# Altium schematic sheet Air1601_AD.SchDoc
size 431 x 279 mm
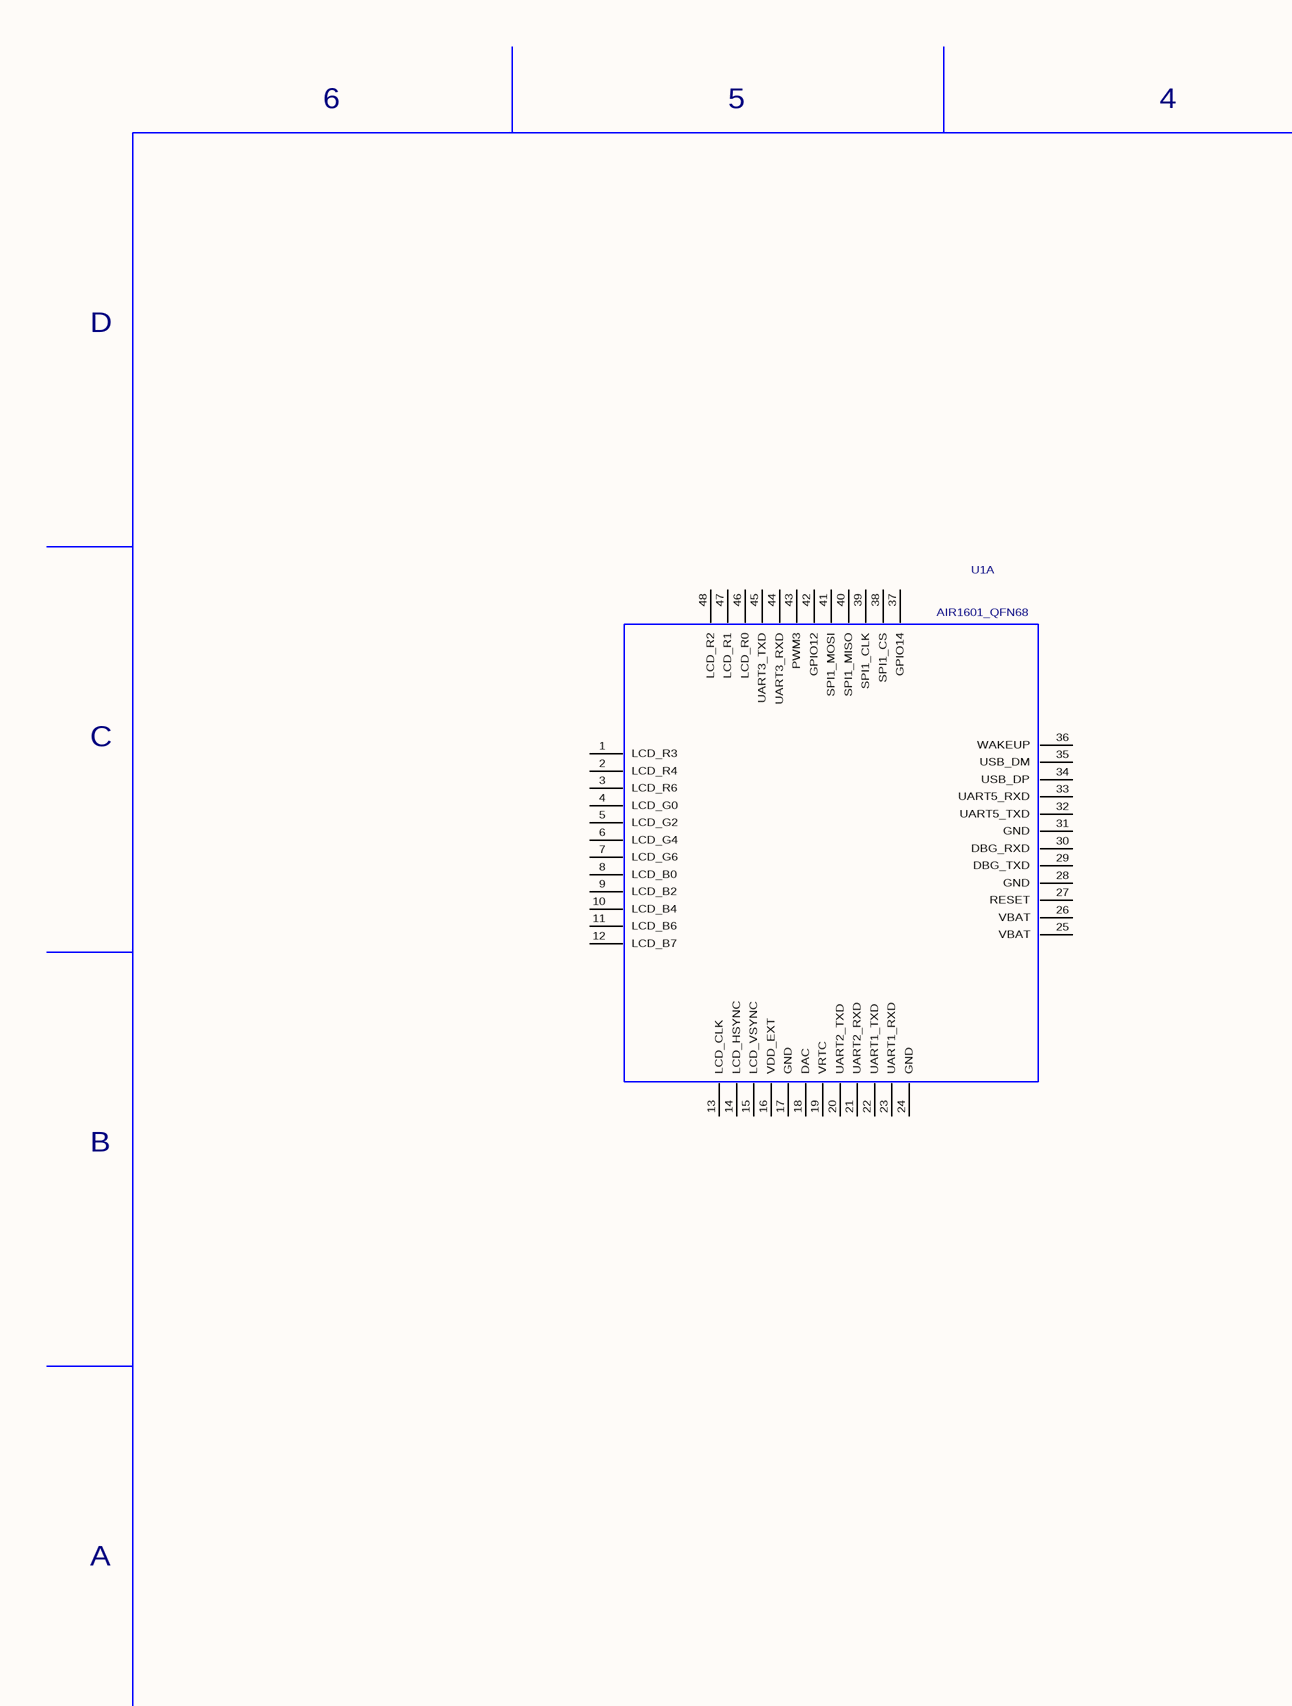
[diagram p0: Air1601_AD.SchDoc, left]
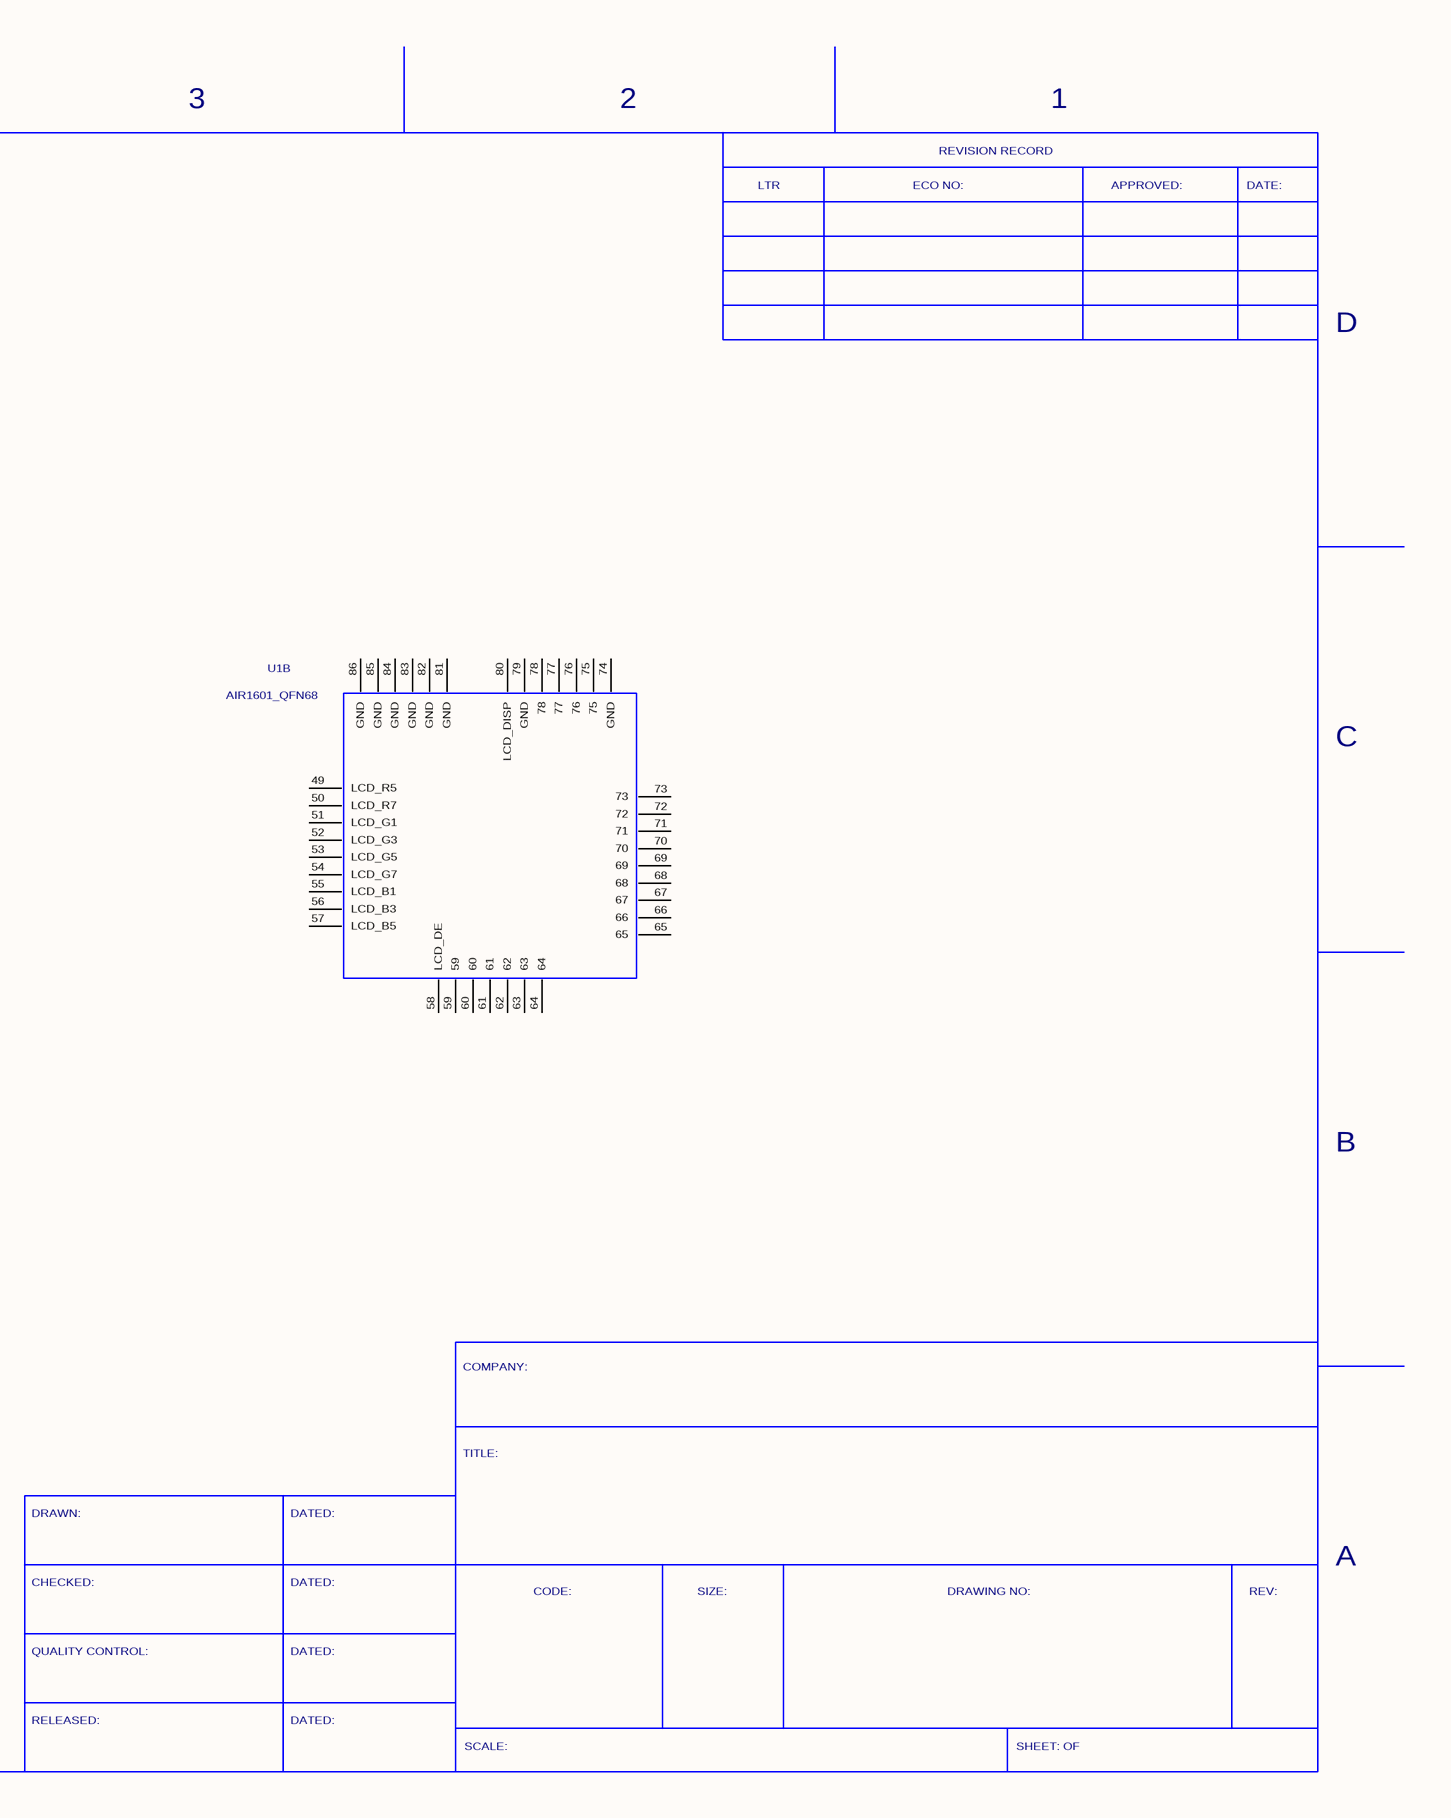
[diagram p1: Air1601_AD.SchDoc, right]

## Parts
U1  AIR1601_QFN68  [AIR1601_19X20]  (parts A,B of 2)

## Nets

Not connected (* = marked no-connect by the designer): U1 1(LCD_R3) 2(LCD_R4) 3(LCD_R6) 4(LCD_G0) 5(LCD_G2) 6(LCD_G4) 7(LCD_G6) 8(LCD_B0) 9(LCD_B2) 10(LCD_B4) 11(LCD_B6) 12(LCD_B7) 13(LCD_CLK) 14(LCD_HSYNC) 15(LCD_VSYNC) 16(VDD_EXT) 17(GND) 18(DAC) 19(VRTC) 20(UART2_TXD) 21(UART2_RXD) 22(UART1_TXD) 23(UART1_RXD) 24(GND) 25(VBAT) 26(VBAT) 27(RESET) 28(GND) 29(DBG_TXD) 30(DBG_RXD) 31(GND) 32(UART5_TXD) 33(UART5_RXD) 34(USB_DP) 35(USB_DM) 36(WAKEUP) 37(GPIO14) 38(SPI1_CS) 39(SPI1_CLK) 40(SPI1_MISO) 41(SPI1_MOSI) 42(GPIO12) 43(PWM3) 44(UART3_RXD) 45(UART3_TXD) 46(LCD_R0) 47(LCD_R1) 48(LCD_R2) 49(LCD_R5) 50(LCD_R7) 51(LCD_G1) 52(LCD_G3) 53(LCD_G5) 54(LCD_G7) 55(LCD_B1) 56(LCD_B3) 57(LCD_B5) 58(LCD_DE) 59 60 61 62 63 64 65 66 67 68 69 70 71 72 73 74(GND) 75 76 77 78 79(GND) 80(LCD_DISP) 81(GND) 82(GND) 83(GND) 84(GND) 85(GND) 86(GND)

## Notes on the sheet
- 6
- 5
- 4
- 3
- 2
- REVISION RECORD
- 1
- LTR
- ECO NO:
- APPROVED:
- DATE:
- D
- C
- B
- COMPANY:
- TITLE:
- DRAWN:
- DATED:
- A
- CHECKED:
- CODE:
- SIZE:
- DRAWING NO:
- REV:
- QUALITY CONTROL:
- RELEASED:
- SCALE:
- SHEET: OF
